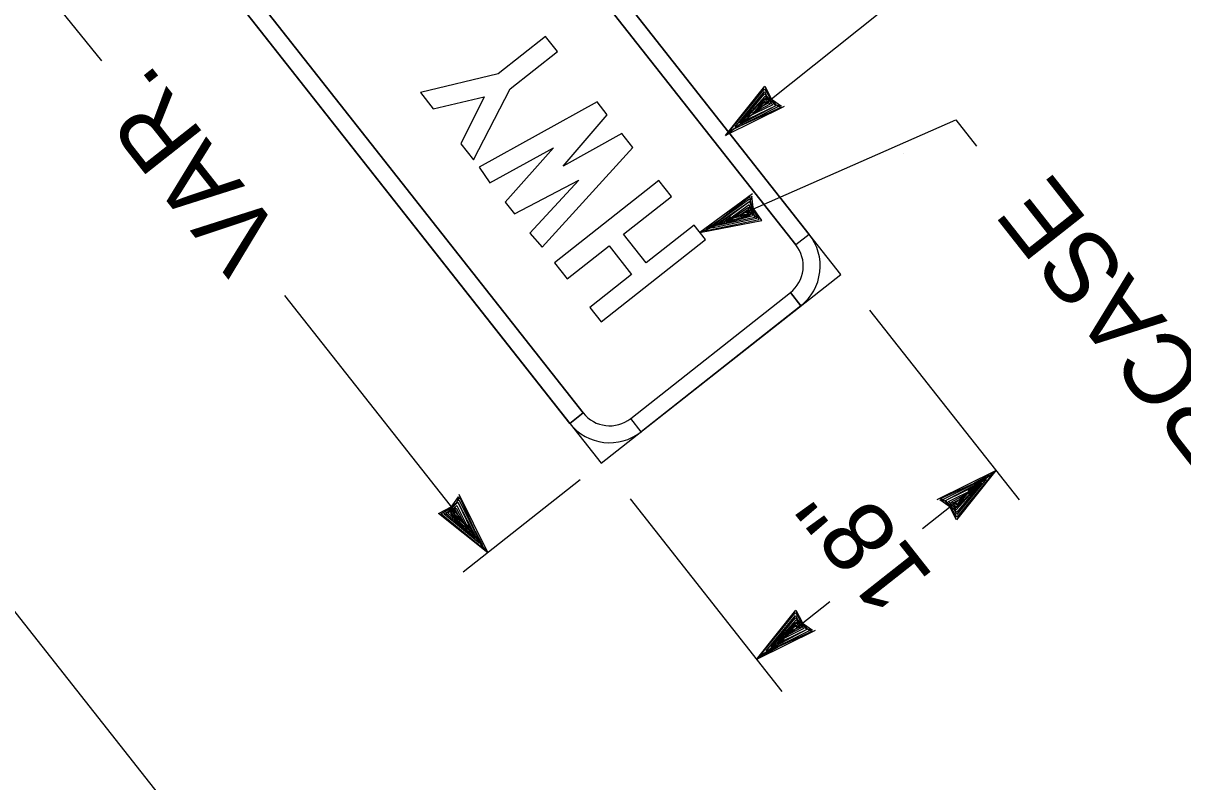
# Model space of a CAD drawing. Extents: x 671946 to 673995, y 1673066 to 1674936.
# Drawn here: x 672609.4 to 672677.9, y 1673527.2 to 1673572 of the extents above; entities that cross this region are included whole.
import ezdxf

# ---------------------------------------------------------------- set-up
doc = ezdxf.new("R2010")
doc.units = 0
for name, color, linetype in [('C-ANNO-SYMB', 7, 'Continuous'), ('Level 1', 7, 'Continuous'), ('V-SIGNAL-LOOP', 7, 'Continuous')]:
    doc.layers.add(name, color=color, linetype=linetype)

msp = doc.modelspace()

# ---------------------------------------------------------------- linework, layer by layer
at = {"layer": 'C-ANNO-SYMB'}
for p, q in [((672657.681, 1673557.137), (672624.249, 1673599.543)), ((672657.681, 1673557.137), (672624.249, 1673599.543)), ((672626.106, 1673597.187), (672655.823, 1673559.492)), ((672655.823, 1673559.492), (672626.106, 1673597.187)), ((672655.038, 1673558.873), (672625.321, 1673596.568)), ((672625.321, 1673596.568), (672655.038, 1673558.873)), ((672610.114, 1673588.399), (672643.545, 1673545.993)), ((672610.114, 1673588.399), (672643.545, 1673545.993)), ((672612.756, 1673586.663), (672642.473, 1673548.968)), ((672642.473, 1673548.968), (672612.756, 1673586.663)), ((672641.688, 1673548.349), (672611.971, 1673586.044)), ((672611.971, 1673586.044), (672641.688, 1673548.349)), ((672655.823, 1673559.492), (672655.038, 1673558.873)), ((672655.823, 1673559.492), (672655.038, 1673558.873)), ((672655.823, 1673559.492), (672655.038, 1673558.873)), ((672655.823, 1673559.492), (672655.038, 1673558.873)), ((672655.038, 1673558.873), (672655.038, 1673558.873)), ((672655.038, 1673558.873), (672655.038, 1673558.873)), ((672655.038, 1673558.873), (672655.038, 1673558.873)), ((672655.038, 1673558.873), (672655.038, 1673558.873)), ((672643.545, 1673545.993), (672657.681, 1673557.137)), ((672643.545, 1673545.993), (672657.681, 1673557.137)), ((672657.681, 1673557.137), (672657.681, 1673557.137)), ((672657.681, 1673557.137), (672657.681, 1673557.137)), ((672657.681, 1673557.137), (672657.681, 1673557.137)), ((672657.681, 1673557.137), (672657.681, 1673557.137)), ((672645.282, 1673548.635), (672654.706, 1673556.065)), ((672645.282, 1673548.635), (672654.706, 1673556.065)), ((672654.706, 1673556.065), (672655.325, 1673555.279)), ((672654.706, 1673556.065), (672655.325, 1673555.279)), ((672654.706, 1673556.065), (672655.325, 1673555.279)), ((672655.325, 1673555.279), (672654.706, 1673556.065)), ((672654.706, 1673556.065), (672655.325, 1673555.279)), ((672655.325, 1673555.279), (672645.901, 1673547.85)), ((672655.325, 1673555.279), (672645.901, 1673547.85)), ((672642.473, 1673548.968), (672641.688, 1673548.349)), ((672642.473, 1673548.968), (672641.688, 1673548.349)), ((672642.473, 1673548.968), (672641.688, 1673548.349)), ((672642.473, 1673548.968), (672641.688, 1673548.349)), ((672641.688, 1673548.349), (672642.473, 1673548.968)), ((672645.901, 1673547.85), (672645.282, 1673548.635)), ((672645.901, 1673547.85), (672645.282, 1673548.635)), ((672645.901, 1673547.85), (672645.282, 1673548.635)), ((672645.282, 1673548.635), (672645.282, 1673548.635)), ((672645.282, 1673548.635), (672645.282, 1673548.635)), ((672645.901, 1673547.85), (672645.282, 1673548.635)), ((672645.282, 1673548.635), (672645.282, 1673548.635)), ((672645.282, 1673548.635), (672645.282, 1673548.635))]:
    msp.add_line(p, q, dxfattribs=at)
for points in [[(672649.568, 1673485.714), (672528.917, 1673638.756), (672514.94, 1673627.737), (672635.591, 1673474.695)], [(672633.627, 1673566.899), (672636.627, 1673567.602), (672635.26, 1673564.828), (672636.003, 1673563.885), (672638.163, 1673568.076), (672640.955, 1673570.277), (672640.254, 1673571.165), (672637.462, 1673568.965), (672632.868, 1673567.862)], [(672633.627, 1673566.899), (672636.627, 1673567.602), (672635.26, 1673564.828), (672636.003, 1673563.885), (672638.163, 1673568.076), (672640.955, 1673570.277), (672640.254, 1673571.165), (672637.462, 1673568.965), (672632.868, 1673567.862)], [(672645.418, 1673564.615), (672644.769, 1673565.438), (672641.3, 1673563.523), (672643.894, 1673566.548), (672643.294, 1673567.309), (672636.343, 1673563.454), (672636.976, 1673562.546), (672640.719, 1673564.609), (672637.878, 1673561.402), (672638.426, 1673560.707), (672642.222, 1673562.702), (672639.323, 1673559.569), (672640.065, 1673558.733)], [(672645.418, 1673564.615), (672644.769, 1673565.438), (672641.3, 1673563.523), (672643.894, 1673566.548), (672643.294, 1673567.309), (672636.343, 1673563.454), (672636.976, 1673562.546), (672640.719, 1673564.609), (672637.878, 1673561.402), (672638.426, 1673560.707), (672642.222, 1673562.702), (672639.323, 1673559.569), (672640.065, 1673558.733)], [(672649.693, 1673559.193), (672649.027, 1673560.038), (672646.199, 1673557.809), (672644.865, 1673559.5), (672647.693, 1673561.73), (672646.95, 1673562.671), (672640.789, 1673557.814), (672641.531, 1673556.872), (672644.002, 1673558.82), (672645.336, 1673557.128), (672642.865, 1673555.18), (672643.531, 1673554.335)], [(672649.693, 1673559.193), (672649.027, 1673560.038), (672646.199, 1673557.809), (672644.865, 1673559.5), (672647.693, 1673561.73), (672646.95, 1673562.671), (672640.789, 1673557.814), (672641.531, 1673556.872), (672644.002, 1673558.82), (672645.336, 1673557.128), (672642.865, 1673555.18), (672643.531, 1673554.335)]]:
    msp.add_lwpolyline(points, close=True, dxfattribs=at)
for centre, radius, start, end in [((672653.467, 1673557.635), 3, 308.25039, 38.2506), ((672653.467, 1673557.635), 3, 308.25039, 38.2506), ((672653.467, 1673557.635), 2, 308.25039, 38.2506), ((672653.467, 1673557.635), 2, 308.25039, 38.2506), ((672644.044, 1673550.206), 2, 218.25075, 308.25039), ((672644.044, 1673550.206), 2, 218.25075, 308.25039), ((672644.044, 1673550.206), 3, 218.25075, 308.25039), ((672644.044, 1673550.206), 3, 218.25075, 308.25039)]:
    msp.add_arc(centre, radius, start, end, dxfattribs=at)
at = {"layer": 'Level 1'}
for p, q in [((672614.061, 1673569.737), (672603.274, 1673583.099)), ((672650.873, 1673565.326), (672653.192, 1673568.236)), ((672651.09, 1673565.562), (672653.174, 1673568.087)), ((672651.441, 1673565.838), (672653.171, 1673567.919)), ((672651.732, 1673566.061), (672653.173, 1673567.787)), ((672653.171, 1673567.919), (672653.309, 1673567.659)), ((672653.173, 1673567.787), (672653.854, 1673567.089)), ((672653.174, 1673568.087), (672653.515, 1673567.522)), ((672653.192, 1673568.236), (672653.585, 1673567.477)), ((672654.333, 1673567.031), (672650.873, 1673565.326)), ((672653.975, 1673567.017), (672651.132, 1673565.594)), ((672651.66, 1673565.938), (672653.214, 1673567.654)), ((672653.854, 1673567.089), (672651.66, 1673565.938)), ((672653.854, 1673567.089), (672651.732, 1673566.061)), ((672652.165, 1673566.401), (672653.159, 1673567.509)), ((672653.675, 1673567.148), (672652.165, 1673566.401)), ((672652.552, 1673566.67), (672653.124, 1673567.382)), ((672653.512, 1673567.187), (672652.552, 1673566.67)), ((672653.217, 1673567.522), (672652.712, 1673566.764)), ((672652.888, 1673566.966), (672653.154, 1673567.305)), ((672653.405, 1673567.237), (672652.888, 1673566.966)), ((672653.124, 1673567.382), (672653.405, 1673567.237)), ((672653.154, 1673567.305), (672653.236, 1673567.24)), ((672653.159, 1673567.509), (672653.512, 1673567.187)), ((672653.214, 1673567.654), (672653.675, 1673567.148)), ((672653.593, 1673567.251), (672653.217, 1673567.522)), ((672653.236, 1673567.24), (672653.593, 1673567.251)), ((672653.309, 1673567.659), (672653.854, 1673567.089)), ((672653.515, 1673567.522), (672654.186, 1673567.05)), ((672653.585, 1673567.477), (672653.826, 1673567.167)), ((672653.826, 1673567.167), (672654.141, 1673566.979)), ((672654.186, 1673567.05), (672653.967, 1673567.113)), ((672653.967, 1673567.113), (672653.975, 1673567.017)), ((672654.141, 1673566.979), (672651.293, 1673565.686)), ((672652.712, 1673566.764), (672652.459, 1673566.663)), ((672652.48, 1673561.885), (672649.36, 1673559.615)), ((672652.301, 1673561.575), (672649.718, 1673559.72)), ((672652.344, 1673561.739), (672649.874, 1673559.82)), ((672652.381, 1673561.523), (672652.301, 1673561.575)), ((672652.364, 1673561.373), (672652.344, 1673561.739)), ((672652.427, 1673561.746), (672652.381, 1673561.523)), ((672652.533, 1673560.932), (672652.427, 1673561.746)), ((672652.308, 1673561.434), (672650.268, 1673560.028)), ((672652.308, 1673561.434), (672650.41, 1673560.033)), ((672652.276, 1673561.248), (672650.913, 1673560.259)), ((672652.236, 1673561.086), (672651.331, 1673560.477)), ((672652.229, 1673560.968), (672651.749, 1673560.636)), ((672652.154, 1673560.816), (672652.33, 1673561.128)), ((672652.227, 1673560.651), (672652.229, 1673560.968)), ((672652.356, 1673560.623), (672652.236, 1673561.086)), ((672652.51, 1673560.605), (672652.276, 1673561.248)), ((672652.559, 1673560.687), (672652.308, 1673561.434)), ((672652.609, 1673560.506), (672652.308, 1673561.434)), ((672652.33, 1673561.128), (672652.395, 1673560.669)), ((672652.525, 1673561.015), (672652.364, 1673561.373)), ((672653.015, 1673560.315), (672652.525, 1673561.015)), ((672652.875, 1673560.368), (672652.533, 1673560.932)), ((672649.36, 1673559.615), (672653.015, 1673560.315)), ((672649.67, 1673559.698), (672652.875, 1673560.368)), ((672649.84, 1673559.89), (672650.588, 1673560.4)), ((672650.077, 1673559.881), (672652.725, 1673560.444)), ((672650.588, 1673560.4), (672650.077, 1673559.881)), ((672650.268, 1673560.028), (672652.51, 1673560.605)), ((672650.41, 1673560.033), (672652.609, 1673560.506)), ((672650.805, 1673560.239), (672651.192, 1673560.528)), ((672651.281, 1673560.397), (672650.805, 1673560.239)), ((672650.913, 1673560.259), (672652.356, 1673560.623)), ((672651.488, 1673560.574), (672651.281, 1673560.397)), ((672651.331, 1673560.477), (672652.227, 1673560.651)), ((672652.395, 1673560.669), (672651.488, 1673560.574)), ((672651.749, 1673560.636), (672652.173, 1673560.713)), ((672652.173, 1673560.713), (672652.154, 1673560.816)), ((672652.725, 1673560.444), (672652.559, 1673560.687)), ((672649.874, 1673559.82), (672649.67, 1673559.698)), ((672649.718, 1673559.72), (672649.84, 1673559.89)), ((672636.841, 1673540.707), (672624.873, 1673555.888)), ((672659.38, 1673555.03), (672668.209, 1673543.831)), ((672662.501, 1673542.144), (672666.841, 1673545.565)), ((672663.379, 1673543.862), (672666.841, 1673545.565)), ((672663.571, 1673543.914), (672666.42, 1673545.206)), ((672663.737, 1673543.876), (672666.581, 1673545.298)), ((672666.841, 1673545.565), (672664.519, 1673542.657)), ((672666.623, 1673545.33), (672664.538, 1673542.805)), ((672666.374, 1673545.268), (672665.574, 1673544.844)), ((672666.581, 1673545.298), (672666.374, 1673545.268)), ((672666.42, 1673545.206), (672666.623, 1673545.33)), ((672642.301, 1673545.012), (672635.397, 1673539.569)), ((672663.858, 1673543.804), (672666.053, 1673544.954)), ((672663.858, 1673543.804), (672665.981, 1673544.831)), ((672664.037, 1673543.745), (672665.547, 1673544.491)), ((672666.053, 1673544.954), (672664.498, 1673543.239)), ((672665.981, 1673544.831), (672664.539, 1673543.105)), ((672666.272, 1673545.054), (672664.541, 1673542.974)), ((672665.547, 1673544.491), (672664.553, 1673543.383)), ((672665.615, 1673544.577), (672665.18, 1673544.369)), ((672665.254, 1673544.229), (672665.615, 1673544.577)), ((672665.574, 1673544.844), (672666.272, 1673545.054)), ((672634.646, 1673543.351), (672635.119, 1673544.022)), ((672635.002, 1673543.662), (672635.19, 1673543.977)), ((672635.119, 1673544.022), (672635.056, 1673543.803)), ((672635.056, 1673543.803), (672635.151, 1673543.811)), ((672635.137, 1673544.169), (672636.841, 1673540.707)), ((672635.151, 1673543.811), (672636.573, 1673540.967)), ((672635.19, 1673543.977), (672636.481, 1673541.128)), ((672645.244, 1673543.886), (672654.2, 1673532.526)), ((672664.197, 1673543.371), (672663.526, 1673543.844)), ((672663.526, 1673543.844), (672663.745, 1673543.78)), ((672663.886, 1673543.726), (672663.571, 1673543.914)), ((672663.745, 1673543.78), (672663.737, 1673543.876)), ((672664.403, 1673543.234), (672663.858, 1673543.804)), ((672664.539, 1673543.105), (672663.858, 1673543.804)), ((672664.498, 1673543.239), (672664.037, 1673543.745)), ((672664.2, 1673543.705), (672665.16, 1673544.222)), ((672664.307, 1673543.656), (672664.824, 1673543.927)), ((672664.495, 1673543.371), (672665.001, 1673544.129)), ((672664.824, 1673543.927), (672664.558, 1673543.587)), ((672665.16, 1673544.222), (672664.588, 1673543.51)), ((672665.001, 1673544.129), (672665.254, 1673544.229)), ((672633.932, 1673543.029), (672634.692, 1673543.421)), ((672634.081, 1673543.011), (672634.646, 1673543.351)), ((672634.249, 1673543.008), (672634.509, 1673543.146)), ((672634.381, 1673543.009), (672635.079, 1673543.69)), ((672634.509, 1673543.146), (672635.079, 1673543.69)), ((672634.514, 1673543.051), (672635.02, 1673543.511)), ((672636.229, 1673541.495), (672634.514, 1673543.051)), ((672634.917, 1673543.43), (672634.646, 1673543.054)), ((672634.646, 1673543.054), (672635.404, 1673542.548)), ((672634.659, 1673542.995), (672634.981, 1673543.349)), ((672634.692, 1673543.421), (672635.002, 1673543.662)), ((672634.786, 1673542.96), (672634.931, 1673543.241)), ((672634.863, 1673542.99), (672634.928, 1673543.072)), ((672634.928, 1673543.072), (672634.917, 1673543.43)), ((672634.931, 1673543.241), (672635.202, 1673542.724)), ((672634.981, 1673543.349), (672635.498, 1673542.388)), ((672635.02, 1673543.511), (672635.767, 1673542.001)), ((672635.079, 1673543.69), (672636.106, 1673541.567)), ((672635.079, 1673543.69), (672636.229, 1673541.495)), ((672664.127, 1673543.416), (672663.886, 1673543.726)), ((672664.476, 1673543.652), (672664.119, 1673543.642)), ((672664.119, 1673543.642), (672664.495, 1673543.371)), ((672664.519, 1673542.657), (672664.127, 1673543.416)), ((672664.538, 1673542.805), (672664.197, 1673543.371)), ((672664.553, 1673543.383), (672664.2, 1673543.705)), ((672664.588, 1673543.51), (672664.307, 1673543.656)), ((672664.541, 1673542.974), (672664.403, 1673543.234)), ((672664.558, 1673543.587), (672664.476, 1673543.652)), ((672636.841, 1673540.707), (672633.932, 1673543.029)), ((672636.605, 1673540.925), (672634.081, 1673543.011)), ((672636.329, 1673541.277), (672634.249, 1673543.008)), ((672636.106, 1673541.567), (672634.381, 1673543.009)), ((672635.767, 1673542.001), (672634.659, 1673542.995)), ((672635.498, 1673542.388), (672634.786, 1673542.96)), ((672635.202, 1673542.724), (672634.863, 1673542.99)), ((672635.404, 1673542.548), (672635.505, 1673542.294)), ((672635.852, 1673541.933), (672635.645, 1673542.368)), ((672635.505, 1673542.294), (672635.852, 1673541.933)), ((672636.544, 1673541.175), (672636.119, 1673541.974)), ((672636.119, 1673541.974), (672636.329, 1673541.277)), ((672636.481, 1673541.128), (672636.605, 1673540.925)), ((672636.573, 1673540.967), (672636.544, 1673541.175)), ((672652.705, 1673534.422), (672657.031, 1673537.831)), ((672652.705, 1673534.422), (672655.027, 1673537.33)), ((672652.923, 1673534.658), (672655.008, 1673537.182)), ((672653.274, 1673534.933), (672655.006, 1673537.013)), ((672655.006, 1673537.013), (672655.144, 1673536.753)), ((672655.008, 1673537.182), (672655.349, 1673536.616)), ((672655.027, 1673537.33), (672655.419, 1673536.571)), ((672653.493, 1673535.033), (672655.048, 1673536.748)), ((672653.565, 1673535.157), (672655.007, 1673536.882)), ((672653.999, 1673535.496), (672654.993, 1673536.604)), ((672655.509, 1673536.242), (672653.999, 1673535.496)), ((672654.386, 1673535.765), (672654.958, 1673536.477)), ((672655.346, 1673536.282), (672654.386, 1673535.765)), ((672655.052, 1673536.616), (672654.546, 1673535.858)), ((672654.722, 1673536.06), (672654.988, 1673536.4)), ((672655.239, 1673536.331), (672654.722, 1673536.06)), ((672654.958, 1673536.477), (672655.239, 1673536.331)), ((672654.988, 1673536.4), (672655.07, 1673536.335)), ((672654.993, 1673536.604), (672655.346, 1673536.282)), ((672655.007, 1673536.882), (672655.688, 1673536.183)), ((672655.048, 1673536.748), (672655.509, 1673536.242)), ((672655.427, 1673536.345), (672655.052, 1673536.616)), ((672655.07, 1673536.335), (672655.427, 1673536.345)), ((672655.144, 1673536.753), (672655.688, 1673536.183)), ((672655.349, 1673536.616), (672656.02, 1673536.143)), ((672655.419, 1673536.571), (672655.66, 1673536.261)), ((672655.66, 1673536.261), (672655.975, 1673536.073)), ((672656.02, 1673536.143), (672655.801, 1673536.207)), ((672655.801, 1673536.207), (672655.809, 1673536.111)), ((672656.167, 1673536.125), (672652.705, 1673534.422)), ((672655.809, 1673536.111), (672652.965, 1673534.689)), ((672655.975, 1673536.073), (672653.126, 1673534.781)), ((672655.688, 1673536.183), (672653.493, 1673535.033)), ((672655.688, 1673536.183), (672653.565, 1673535.157)), ((672654.292, 1673535.758), (672653.931, 1673535.41)), ((672653.931, 1673535.41), (672654.366, 1673535.618)), ((672654.546, 1673535.858), (672654.292, 1673535.758)), ((672653.172, 1673534.719), (672653.972, 1673535.144)), ((672653.972, 1673535.144), (672653.274, 1673534.933)), ((672653.126, 1673534.781), (672652.923, 1673534.658)), ((672652.965, 1673534.689), (672653.172, 1673534.719))]:
    msp.add_line(p, q, dxfattribs=at)
for points in [[(672650.873, 1673565.326), (672659.985, 1673572.586), (672656.848, 1673576.443)], [(672649.36, 1673559.615), (672664.468, 1673566.252), (672665.69, 1673564.701)]]:
    msp.add_lwpolyline(points, dxfattribs=at)
at = {"layer": 'V-SIGNAL-LOOP'}
msp.add_lwpolyline([(672661.394, 1673564.266), (672661.394, 1673564.266), (672661.394, 1673564.266)], dxfattribs=at)

# ---------------------------------------------------------------- texts
at = {"layer": 'Level 1'}
for s, p in [('VAR.', (672624.855, 1673559.4)), ('8" UPPERCASE', (672695.612, 1673530.753)), ('18"', (672663.25, 1673539.26))]:
    msp.add_text(s, height=4.2, rotation=128.25054, dxfattribs=at).set_placement(p)

doc.saveas('drawing.dxf')
